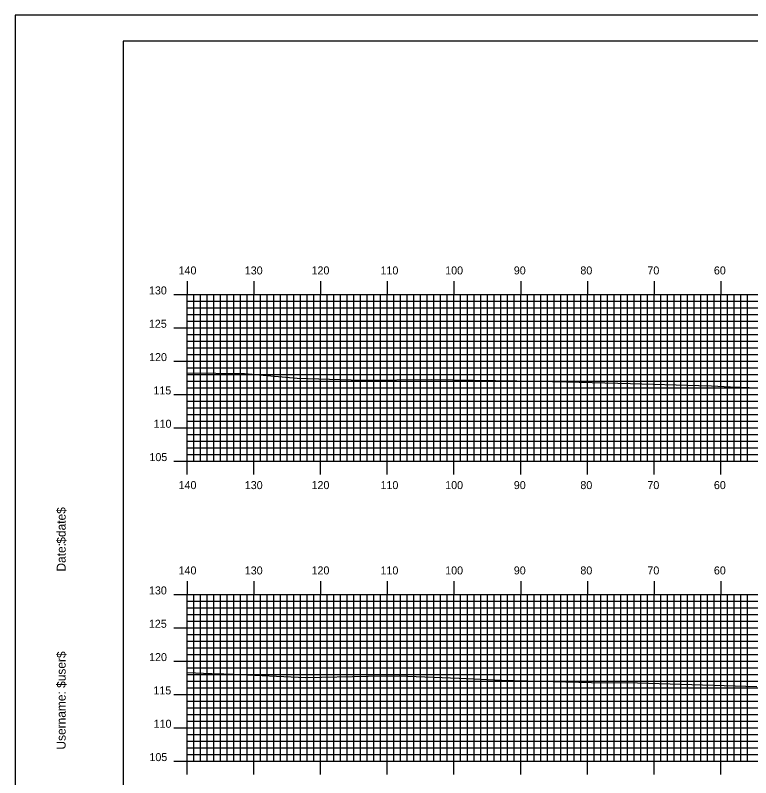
# Model space of a CAD drawing. Extents: x 1771235 to 1771579, y 442591 to 442811.
# Drawn here: x 1771235.3 to 1771345.6, y 442696.2 to 442810.5 of the extents above; entities that cross this region are included whole.
import ezdxf

# ---------------------------------------------------------------- set-up
doc = ezdxf.new("R2010")
doc.units = 0
for name, color, linetype in [('BORDER', 7, 'Continuous'), ('H_V ANNOTATION', 7, 'Continuous'), ('MAJOR', 7, 'Continuous'), ('MINOR', 7, 'Continuous'), ('PLOT BOUNDARY', 7, 'Continuous'), ('S_Roadway_Centerline', 7, 'Continuous')]:
    doc.layers.add(name, color=color, linetype=linetype)

msp = doc.modelspace()

# ---------------------------------------------------------------- linework, layer by layer
at = {"layer": 'BORDER'}
msp.add_lwpolyline([(1771251.47, 442596.67), (1771571.47, 442596.67), (1771571.47, 442806.67), (1771251.47, 442806.67)], close=True, dxfattribs=at)
at = {"layer": 'MAJOR'}
for p, q in [((1771261.07, 442770.67), (1771261.07, 442768.67)), ((1771271.07, 442770.67), (1771271.07, 442768.67)), ((1771281.07, 442770.67), (1771281.07, 442768.67)), ((1771291.07, 442770.67), (1771291.07, 442768.67)), ((1771301.07, 442770.67), (1771301.07, 442768.67)), ((1771311.07, 442770.67), (1771311.07, 442768.67)), ((1771321.07, 442770.67), (1771321.07, 442768.67)), ((1771331.07, 442770.67), (1771331.07, 442768.67)), ((1771341.07, 442770.67), (1771341.07, 442768.67)), ((1771259.06, 442768.67), (1771261.07, 442768.67)), ((1771261.07, 442768.67), (1771541.07, 442768.67)), ((1771261.07, 442743.67), (1771261.07, 442768.67)), ((1771261.07, 442743.67), (1771261.07, 442768.67)), ((1771261.07, 442768.67), (1771541.07, 442768.67)), ((1771271.07, 442743.67), (1771271.07, 442768.67)), ((1771281.07, 442743.67), (1771281.07, 442768.67)), ((1771291.07, 442743.67), (1771291.07, 442768.67)), ((1771301.07, 442743.67), (1771301.07, 442768.67)), ((1771311.07, 442743.67), (1771311.07, 442768.67)), ((1771321.07, 442743.67), (1771321.07, 442768.67)), ((1771331.07, 442743.67), (1771331.07, 442768.67)), ((1771341.07, 442743.67), (1771341.07, 442768.67)), ((1771259.06, 442763.67), (1771261.07, 442763.67)), ((1771261.07, 442763.67), (1771541.07, 442763.67)), ((1771259.06, 442758.67), (1771261.07, 442758.67)), ((1771261.07, 442758.67), (1771541.07, 442758.67)), ((1771259.06, 442753.67), (1771261.07, 442753.67)), ((1771261.07, 442753.67), (1771541.07, 442753.67)), ((1771259.06, 442748.67), (1771261.07, 442748.67)), ((1771261.07, 442748.67), (1771541.07, 442748.67)), ((1771259.06, 442743.67), (1771261.07, 442743.67)), ((1771261.07, 442743.67), (1771541.07, 442743.67)), ((1771261.07, 442743.67), (1771541.07, 442743.67)), ((1771261.07, 442741.66), (1771261.07, 442743.67)), ((1771271.07, 442741.66), (1771271.07, 442743.67)), ((1771281.07, 442741.66), (1771281.07, 442743.67)), ((1771291.07, 442741.66), (1771291.07, 442743.67)), ((1771301.07, 442741.66), (1771301.07, 442743.67)), ((1771311.07, 442741.66), (1771311.07, 442743.67)), ((1771321.07, 442741.66), (1771321.07, 442743.67)), ((1771331.07, 442741.66), (1771331.07, 442743.67)), ((1771341.07, 442741.66), (1771341.07, 442743.67)), ((1771261.07, 442725.67), (1771261.07, 442723.67)), ((1771271.07, 442725.67), (1771271.07, 442723.67)), ((1771281.07, 442725.67), (1771281.07, 442723.67)), ((1771291.07, 442725.67), (1771291.07, 442723.67)), ((1771301.07, 442725.67), (1771301.07, 442723.67)), ((1771311.07, 442725.67), (1771311.07, 442723.67)), ((1771321.07, 442725.67), (1771321.07, 442723.67)), ((1771331.07, 442725.67), (1771331.07, 442723.67)), ((1771341.07, 442725.67), (1771341.07, 442723.67)), ((1771259.06, 442723.67), (1771261.07, 442723.67)), ((1771261.07, 442723.67), (1771541.07, 442723.67)), ((1771261.07, 442698.67), (1771261.07, 442723.67)), ((1771261.07, 442698.67), (1771261.07, 442723.67)), ((1771261.07, 442723.67), (1771541.07, 442723.67)), ((1771271.07, 442698.67), (1771271.07, 442723.67)), ((1771281.07, 442698.67), (1771281.07, 442723.67)), ((1771291.07, 442698.67), (1771291.07, 442723.67)), ((1771301.07, 442698.67), (1771301.07, 442723.67)), ((1771311.07, 442698.67), (1771311.07, 442723.67)), ((1771321.07, 442698.67), (1771321.07, 442723.67)), ((1771331.07, 442698.67), (1771331.07, 442723.67)), ((1771341.07, 442698.67), (1771341.07, 442723.67)), ((1771259.06, 442718.67), (1771261.07, 442718.67)), ((1771261.07, 442718.67), (1771541.07, 442718.67)), ((1771259.06, 442713.67), (1771261.07, 442713.67)), ((1771261.07, 442713.67), (1771541.07, 442713.67)), ((1771259.06, 442708.67), (1771261.07, 442708.67)), ((1771261.07, 442708.67), (1771541.07, 442708.67)), ((1771259.06, 442703.67), (1771261.07, 442703.67)), ((1771261.07, 442703.67), (1771541.07, 442703.67)), ((1771259.06, 442698.67), (1771261.07, 442698.67)), ((1771261.07, 442698.67), (1771541.07, 442698.67)), ((1771261.07, 442698.67), (1771541.07, 442698.67)), ((1771261.07, 442696.66), (1771261.07, 442698.67)), ((1771271.07, 442696.66), (1771271.07, 442698.67)), ((1771281.07, 442696.66), (1771281.07, 442698.67)), ((1771291.07, 442696.66), (1771291.07, 442698.67)), ((1771301.07, 442696.66), (1771301.07, 442698.67)), ((1771311.07, 442696.66), (1771311.07, 442698.67)), ((1771321.07, 442696.66), (1771321.07, 442698.67)), ((1771331.07, 442696.66), (1771331.07, 442698.67)), ((1771341.07, 442696.66), (1771341.07, 442698.67))]:
    msp.add_line(p, q, dxfattribs=at)
at = {"layer": 'MINOR'}
for p, q in [((1771261.07, 442767.67), (1771541.07, 442767.67)), ((1771261.07, 442767.67), (1771263.07, 442767.67)), ((1771262.07, 442743.67), (1771262.07, 442768.67)), ((1771263.07, 442743.67), (1771263.07, 442768.67)), ((1771264.07, 442743.67), (1771264.07, 442768.67)), ((1771265.07, 442743.67), (1771265.07, 442768.67)), ((1771266.07, 442743.67), (1771266.07, 442768.67)), ((1771267.07, 442743.67), (1771267.07, 442768.67)), ((1771268.07, 442743.67), (1771268.07, 442768.67)), ((1771269.07, 442743.67), (1771269.07, 442768.67)), ((1771270.07, 442743.67), (1771270.07, 442768.67)), ((1771272.07, 442743.67), (1771272.07, 442768.67)), ((1771273.07, 442743.67), (1771273.07, 442768.67)), ((1771274.07, 442743.67), (1771274.07, 442768.67)), ((1771275.07, 442743.67), (1771275.07, 442768.67)), ((1771276.07, 442743.67), (1771276.07, 442768.67)), ((1771277.07, 442743.67), (1771277.07, 442768.67)), ((1771278.07, 442743.67), (1771278.07, 442768.67)), ((1771279.07, 442743.67), (1771279.07, 442768.67)), ((1771280.07, 442743.67), (1771280.07, 442768.67)), ((1771282.07, 442743.67), (1771282.07, 442768.67)), ((1771283.07, 442743.67), (1771283.07, 442768.67)), ((1771284.07, 442743.67), (1771284.07, 442768.67)), ((1771285.07, 442743.67), (1771285.07, 442768.67)), ((1771286.07, 442743.67), (1771286.07, 442768.67)), ((1771287.07, 442743.67), (1771287.07, 442768.67)), ((1771288.07, 442743.67), (1771288.07, 442768.67)), ((1771289.07, 442743.67), (1771289.07, 442768.67)), ((1771290.07, 442743.67), (1771290.07, 442768.67)), ((1771292.07, 442743.67), (1771292.07, 442768.67)), ((1771293.07, 442743.67), (1771293.07, 442768.67)), ((1771294.07, 442743.67), (1771294.07, 442768.67)), ((1771295.07, 442743.67), (1771295.07, 442768.67)), ((1771296.07, 442743.67), (1771296.07, 442768.67)), ((1771297.07, 442743.67), (1771297.07, 442768.67)), ((1771298.07, 442743.67), (1771298.07, 442768.67)), ((1771299.07, 442743.67), (1771299.07, 442768.67)), ((1771300.07, 442743.67), (1771300.07, 442768.67)), ((1771302.07, 442743.67), (1771302.07, 442768.67)), ((1771303.07, 442743.67), (1771303.07, 442768.67)), ((1771304.07, 442743.67), (1771304.07, 442768.67)), ((1771305.07, 442743.67), (1771305.07, 442768.67)), ((1771306.07, 442743.67), (1771306.07, 442768.67)), ((1771307.07, 442743.67), (1771307.07, 442768.67)), ((1771308.07, 442743.67), (1771308.07, 442768.67)), ((1771309.07, 442743.67), (1771309.07, 442768.67)), ((1771310.07, 442743.67), (1771310.07, 442768.67)), ((1771312.07, 442743.67), (1771312.07, 442768.67)), ((1771313.07, 442743.67), (1771313.07, 442768.67)), ((1771314.07, 442743.67), (1771314.07, 442768.67)), ((1771315.07, 442743.67), (1771315.07, 442768.67)), ((1771316.07, 442743.67), (1771316.07, 442768.67)), ((1771317.07, 442743.67), (1771317.07, 442768.67)), ((1771318.07, 442743.67), (1771318.07, 442768.67)), ((1771319.07, 442743.67), (1771319.07, 442768.67)), ((1771320.07, 442743.67), (1771320.07, 442768.67)), ((1771322.07, 442743.67), (1771322.07, 442768.67)), ((1771323.07, 442743.67), (1771323.07, 442768.67)), ((1771324.07, 442743.67), (1771324.07, 442768.67)), ((1771325.07, 442743.67), (1771325.07, 442768.67)), ((1771326.07, 442743.67), (1771326.07, 442768.67)), ((1771327.07, 442743.67), (1771327.07, 442768.67)), ((1771328.07, 442743.67), (1771328.07, 442768.67)), ((1771329.07, 442743.67), (1771329.07, 442768.67)), ((1771330.07, 442743.67), (1771330.07, 442768.67)), ((1771332.07, 442743.67), (1771332.07, 442768.67)), ((1771333.07, 442743.67), (1771333.07, 442768.67)), ((1771334.07, 442743.67), (1771334.07, 442768.67)), ((1771335.07, 442743.67), (1771335.07, 442768.67)), ((1771336.07, 442743.67), (1771336.07, 442768.67)), ((1771337.07, 442743.67), (1771337.07, 442768.67)), ((1771338.07, 442743.67), (1771338.07, 442768.67)), ((1771339.07, 442743.67), (1771339.07, 442768.67)), ((1771340.07, 442743.67), (1771340.07, 442768.67)), ((1771342.07, 442743.67), (1771342.07, 442768.67)), ((1771343.07, 442743.67), (1771343.07, 442768.67)), ((1771344.07, 442743.67), (1771344.07, 442768.67)), ((1771345.07, 442743.67), (1771345.07, 442768.67)), ((1771261.07, 442766.67), (1771541.07, 442766.67)), ((1771261.07, 442766.67), (1771263.07, 442766.67)), ((1771261.07, 442765.67), (1771541.07, 442765.67)), ((1771261.07, 442765.67), (1771263.07, 442765.67)), ((1771261.07, 442764.67), (1771541.07, 442764.67)), ((1771261.07, 442764.67), (1771263.07, 442764.67)), ((1771261.07, 442762.67), (1771541.07, 442762.67)), ((1771261.07, 442762.67), (1771263.07, 442762.67)), ((1771261.07, 442761.67), (1771541.07, 442761.67)), ((1771261.07, 442761.67), (1771263.07, 442761.67)), ((1771261.07, 442760.67), (1771541.07, 442760.67)), ((1771261.07, 442760.67), (1771263.07, 442760.67)), ((1771261.07, 442759.67), (1771541.07, 442759.67)), ((1771261.07, 442759.67), (1771263.07, 442759.67)), ((1771261.07, 442757.67), (1771541.07, 442757.67)), ((1771261.07, 442757.67), (1771263.07, 442757.67)), ((1771261.07, 442756.67), (1771541.07, 442756.67)), ((1771261.07, 442756.67), (1771263.07, 442756.67)), ((1771261.07, 442755.67), (1771541.07, 442755.67)), ((1771261.07, 442755.67), (1771263.07, 442755.67)), ((1771261.07, 442754.67), (1771541.07, 442754.67)), ((1771261.07, 442754.67), (1771263.07, 442754.67)), ((1771261.07, 442752.67), (1771541.07, 442752.67)), ((1771261.07, 442752.67), (1771263.07, 442752.67)), ((1771261.07, 442751.67), (1771541.07, 442751.67)), ((1771261.07, 442751.67), (1771263.07, 442751.67)), ((1771261.07, 442750.67), (1771541.07, 442750.67)), ((1771261.07, 442750.67), (1771263.07, 442750.67)), ((1771261.07, 442749.67), (1771541.07, 442749.67)), ((1771261.07, 442749.67), (1771263.07, 442749.67)), ((1771261.07, 442747.67), (1771541.07, 442747.67)), ((1771261.07, 442747.67), (1771263.07, 442747.67)), ((1771261.07, 442746.67), (1771541.07, 442746.67)), ((1771261.07, 442746.67), (1771263.07, 442746.67)), ((1771261.07, 442745.67), (1771541.07, 442745.67)), ((1771261.07, 442745.67), (1771263.07, 442745.67)), ((1771261.07, 442744.67), (1771541.07, 442744.67)), ((1771261.07, 442744.67), (1771263.07, 442744.67)), ((1771262.07, 442698.67), (1771262.07, 442723.67)), ((1771263.07, 442698.67), (1771263.07, 442723.67)), ((1771264.07, 442698.67), (1771264.07, 442723.67)), ((1771265.07, 442698.67), (1771265.07, 442723.67)), ((1771266.07, 442698.67), (1771266.07, 442723.67)), ((1771267.07, 442698.67), (1771267.07, 442723.67)), ((1771268.07, 442698.67), (1771268.07, 442723.67)), ((1771269.07, 442698.67), (1771269.07, 442723.67)), ((1771270.07, 442698.67), (1771270.07, 442723.67)), ((1771272.07, 442698.67), (1771272.07, 442723.67)), ((1771273.07, 442698.67), (1771273.07, 442723.67)), ((1771274.07, 442698.67), (1771274.07, 442723.67)), ((1771275.07, 442698.67), (1771275.07, 442723.67)), ((1771276.07, 442698.67), (1771276.07, 442723.67)), ((1771277.07, 442698.67), (1771277.07, 442723.67)), ((1771278.07, 442698.67), (1771278.07, 442723.67)), ((1771279.07, 442698.67), (1771279.07, 442723.67)), ((1771280.07, 442698.67), (1771280.07, 442723.67)), ((1771282.07, 442698.67), (1771282.07, 442723.67)), ((1771283.07, 442698.67), (1771283.07, 442723.67)), ((1771284.07, 442698.67), (1771284.07, 442723.67)), ((1771285.07, 442698.67), (1771285.07, 442723.67)), ((1771286.07, 442698.67), (1771286.07, 442723.67)), ((1771287.07, 442698.67), (1771287.07, 442723.67)), ((1771288.07, 442698.67), (1771288.07, 442723.67)), ((1771289.07, 442698.67), (1771289.07, 442723.67)), ((1771290.07, 442698.67), (1771290.07, 442723.67)), ((1771292.07, 442698.67), (1771292.07, 442723.67)), ((1771293.07, 442698.67), (1771293.07, 442723.67)), ((1771294.07, 442698.67), (1771294.07, 442723.67)), ((1771295.07, 442698.67), (1771295.07, 442723.67)), ((1771296.07, 442698.67), (1771296.07, 442723.67)), ((1771297.07, 442698.67), (1771297.07, 442723.67)), ((1771298.07, 442698.67), (1771298.07, 442723.67)), ((1771299.07, 442698.67), (1771299.07, 442723.67)), ((1771300.07, 442698.67), (1771300.07, 442723.67)), ((1771302.07, 442698.67), (1771302.07, 442723.67)), ((1771303.07, 442698.67), (1771303.07, 442723.67)), ((1771304.07, 442698.67), (1771304.07, 442723.67)), ((1771305.07, 442698.67), (1771305.07, 442723.67)), ((1771306.07, 442698.67), (1771306.07, 442723.67)), ((1771307.07, 442698.67), (1771307.07, 442723.67)), ((1771308.07, 442698.67), (1771308.07, 442723.67)), ((1771309.07, 442698.67), (1771309.07, 442723.67)), ((1771310.07, 442698.67), (1771310.07, 442723.67)), ((1771312.07, 442698.67), (1771312.07, 442723.67)), ((1771313.07, 442698.67), (1771313.07, 442723.67)), ((1771314.07, 442698.67), (1771314.07, 442723.67)), ((1771315.07, 442698.67), (1771315.07, 442723.67)), ((1771316.07, 442698.67), (1771316.07, 442723.67)), ((1771317.07, 442698.67), (1771317.07, 442723.67)), ((1771318.07, 442698.67), (1771318.07, 442723.67)), ((1771319.07, 442698.67), (1771319.07, 442723.67)), ((1771320.07, 442698.67), (1771320.07, 442723.67)), ((1771322.07, 442698.67), (1771322.07, 442723.67)), ((1771323.07, 442698.67), (1771323.07, 442723.67)), ((1771324.07, 442698.67), (1771324.07, 442723.67)), ((1771325.07, 442698.67), (1771325.07, 442723.67)), ((1771326.07, 442698.67), (1771326.07, 442723.67)), ((1771327.07, 442698.67), (1771327.07, 442723.67)), ((1771328.07, 442698.67), (1771328.07, 442723.67)), ((1771329.07, 442698.67), (1771329.07, 442723.67)), ((1771330.07, 442698.67), (1771330.07, 442723.67)), ((1771332.07, 442698.67), (1771332.07, 442723.67)), ((1771333.07, 442698.67), (1771333.07, 442723.67)), ((1771334.07, 442698.67), (1771334.07, 442723.67)), ((1771335.07, 442698.67), (1771335.07, 442723.67)), ((1771336.07, 442698.67), (1771336.07, 442723.67)), ((1771337.07, 442698.67), (1771337.07, 442723.67)), ((1771338.07, 442698.67), (1771338.07, 442723.67)), ((1771339.07, 442698.67), (1771339.07, 442723.67)), ((1771340.07, 442698.67), (1771340.07, 442723.67)), ((1771342.07, 442698.67), (1771342.07, 442723.67)), ((1771343.07, 442698.67), (1771343.07, 442723.67)), ((1771344.07, 442698.67), (1771344.07, 442723.67)), ((1771345.07, 442698.67), (1771345.07, 442723.67)), ((1771261.07, 442722.67), (1771541.07, 442722.67)), ((1771261.07, 442722.67), (1771263.07, 442722.67)), ((1771261.07, 442721.67), (1771541.07, 442721.67)), ((1771261.07, 442721.67), (1771263.07, 442721.67)), ((1771261.07, 442720.67), (1771541.07, 442720.67)), ((1771261.07, 442720.67), (1771263.07, 442720.67)), ((1771261.07, 442719.67), (1771541.07, 442719.67)), ((1771261.07, 442719.67), (1771263.07, 442719.67)), ((1771261.07, 442717.67), (1771541.07, 442717.67)), ((1771261.07, 442717.67), (1771263.07, 442717.67)), ((1771261.07, 442716.67), (1771541.07, 442716.67)), ((1771261.07, 442716.67), (1771263.07, 442716.67)), ((1771261.07, 442715.67), (1771541.07, 442715.67)), ((1771261.07, 442715.67), (1771263.07, 442715.67)), ((1771261.07, 442714.67), (1771541.07, 442714.67)), ((1771261.07, 442714.67), (1771263.07, 442714.67)), ((1771261.07, 442712.67), (1771541.07, 442712.67)), ((1771261.07, 442712.67), (1771263.07, 442712.67)), ((1771261.07, 442711.67), (1771541.07, 442711.67)), ((1771261.07, 442711.67), (1771263.07, 442711.67)), ((1771261.07, 442710.67), (1771541.07, 442710.67)), ((1771261.07, 442710.67), (1771263.07, 442710.67)), ((1771261.07, 442709.67), (1771541.07, 442709.67)), ((1771261.07, 442709.67), (1771263.07, 442709.67)), ((1771261.07, 442707.67), (1771541.07, 442707.67)), ((1771261.07, 442707.67), (1771263.07, 442707.67)), ((1771261.07, 442706.67), (1771541.07, 442706.67)), ((1771261.07, 442706.67), (1771263.07, 442706.67)), ((1771261.07, 442705.67), (1771541.07, 442705.67)), ((1771261.07, 442705.67), (1771263.07, 442705.67)), ((1771261.07, 442704.67), (1771541.07, 442704.67)), ((1771261.07, 442704.67), (1771263.07, 442704.67)), ((1771261.07, 442702.67), (1771541.07, 442702.67)), ((1771261.07, 442702.67), (1771263.07, 442702.67)), ((1771261.07, 442701.67), (1771541.07, 442701.67)), ((1771261.07, 442701.67), (1771263.07, 442701.67)), ((1771261.07, 442700.67), (1771541.07, 442700.67)), ((1771261.07, 442700.67), (1771263.07, 442700.67)), ((1771261.07, 442699.67), (1771541.07, 442699.67)), ((1771261.07, 442699.67), (1771263.07, 442699.67))]:
    msp.add_line(p, q, dxfattribs=at)
at = {"layer": 'PLOT BOUNDARY'}
msp.add_lwpolyline([(1771235.28, 442590.55), (1771575.28, 442590.55), (1771575.28, 442810.55), (1771235.28, 442810.55)], close=True, dxfattribs=at)
at = {"layer": 'S_Roadway_Centerline'}
for points in [[(1771261.07, 442756.89), (1771269.66, 442756.8), (1771277.56, 442756.12), (1771287.23, 442755.79), (1771297.69, 442755.92), (1771313.7, 442755.68), (1771317.92, 442755.57), (1771327.56, 442755.3), (1771337.77, 442755), (1771339.66, 442754.96), (1771342.53, 442754.83), (1771352.36, 442754.47)], [(1771261.07, 442711.96), (1771264.76, 442711.79), (1771266.57, 442711.75), (1771267.91, 442711.73), (1771278.87, 442711.23), (1771288.21, 442711.42), (1771292.87, 442711.44), (1771301.86, 442711.11), (1771308.22, 442710.81), (1771321.69, 442710.47), (1771328.59, 442710.41), (1771346.5, 442709.87)]]:
    msp.add_lwpolyline(points, dxfattribs=at)

# ---------------------------------------------------------------- texts
at = {"layer": 'BORDER'}
for s, p in [('$date$', (1771242.84, 442731.28)), ('Date:', (1771242.84, 442727.1)), ('$user$', (1771242.84, 442709.65)), ('Username:', (1771242.84, 442700.4))]:
    msp.add_text(s, height=1.339, rotation=90, dxfattribs=at).set_placement(p)
at = {"layer": 'H_V ANNOTATION'}
for s, p in [('140', (1771259.77, 442771.67)), ('130', (1771269.7, 442771.67)), ('120', (1771279.71, 442771.67)), ('110', (1771290.05, 442771.67)), ('100', (1771299.75, 442771.67)), ('90', (1771310.04, 442771.67)), ('80', (1771320.02, 442771.67)), ('70', (1771330.07, 442771.67)), ('60', (1771340.04, 442771.67)), ('130', (1771255.33, 442768.67)), ('125', (1771255.32, 442763.67)), ('120', (1771255.35, 442758.67)), ('115', (1771256, 442753.67)), ('110', (1771256.03, 442748.67)), ('105', (1771255.4, 442743.67)), ('140', (1771259.77, 442739.47)), ('130', (1771269.7, 442739.47)), ('120', (1771279.71, 442739.47)), ('110', (1771290.05, 442739.47)), ('100', (1771299.75, 442739.47)), ('90', (1771310.04, 442739.47)), ('80', (1771320.02, 442739.47)), ('70', (1771330.07, 442739.47)), ('60', (1771340.04, 442739.47)), ('140', (1771259.77, 442726.67)), ('130', (1771269.7, 442726.67)), ('120', (1771279.71, 442726.67)), ('110', (1771290.05, 442726.67)), ('100', (1771299.75, 442726.67)), ('90', (1771310.04, 442726.67)), ('80', (1771320.02, 442726.67)), ('70', (1771330.07, 442726.67)), ('60', (1771340.04, 442726.67)), ('130', (1771255.33, 442723.67)), ('125', (1771255.32, 442718.67)), ('120', (1771255.35, 442713.67)), ('115', (1771256, 442708.67)), ('110', (1771256.03, 442703.67)), ('105', (1771255.4, 442698.67))]:
    msp.add_text(s, height=1.2, dxfattribs=at).set_placement(p)
at = {"layer": 'MAJOR'}
for p in [(1771261.06, 442743.67), (1771261.06, 442698.67)]:
    msp.add_text('-', height=0.012, dxfattribs=at).set_placement(p)

doc.saveas('drawing.dxf')
